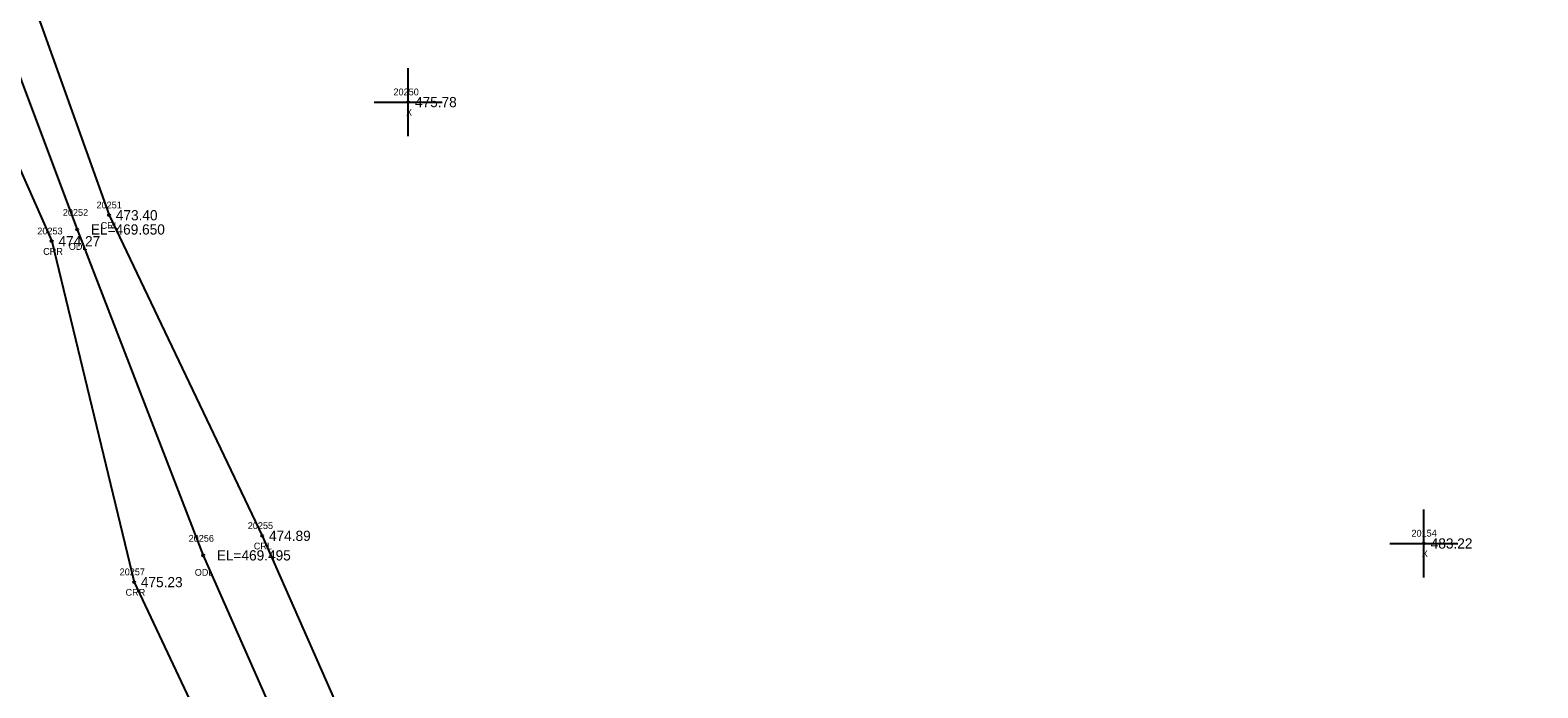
# Model space of a CAD drawing. Extents: x 1789565 to 1790548, y 909019 to 910194.
# Drawn here: x 1789950.9 to 1790172.5, y 909792.3 to 909888.9 of the extents above; entities that cross this region are included whole.
import ezdxf

# ---------------------------------------------------------------- set-up
doc = ezdxf.new("R2010")
doc.units = 0
for name, color, linetype in [('RD_EX_H2O', 7, 'Continuous'), ('RD_EX_H2O_txCode', 7, 'Continuous'), ('RD_EX_Misc', 7, 'Continuous'), ('RD_EX_Misc_txCode', 7, 'Continuous'), ('RD_EX_TX_H2O_ELEV', 7, 'Continuous'), ('RD_EX_TX_Misc_ELEV', 7, 'Continuous'), ('RD_SMD_Locator', 7, 'Continuous')]:
    doc.layers.add(name, color=color, linetype=linetype)

msp = doc.modelspace()

# ---------------------------------------------------------------- linework, layer by layer
at = {"layer": 'RD_EX_H2O'}
for points in [[(1789916.44, 910152.62), (1789911.22, 910059.17), (1789911.57, 910015.4), (1789913.25, 909950.04), (1789954.03, 909857.92), (1789966.14, 909807.85), (1790000.75, 909734.57), (1790025.55, 909650.06), (1790037.59, 909635.91)], [(1789926.75, 910151.78), (1789921.87, 910061.22), (1789923.33, 910015.8), (1789922.65, 909953.15), (1789957.79, 909859.65), (1789976.3, 909811.78), (1790009.05, 909737.59), (1790033.3, 909656.58), (1790043.84, 909640.77), (1790040.94, 909620.44), (1790068.41, 909598.88), (1790105.46, 909552.21), (1790128.28, 909493.4), (1790125.72, 909445.59), (1790167.31, 909436.17), (1790202.14, 909447.88), (1790216.41, 909437.36), (1790196.97, 909382.86), (1790209.47, 909371.8), (1790248.65, 909379.51), (1790333.47, 909404.65), (1790412.72, 909370.84), (1790438.82, 909377.48), (1790480.23, 909327.32)], [(1789942.19, 910149.47), (1789928.94, 910061.47), (1789937.03, 910016.56), (1789929.09, 909954.8), (1789962.46, 909861.74), (1789984.97, 909814.65), (1790017.82, 909740.15), (1790045.4, 909660.05), (1790055.69, 909646.96), (1790055.38, 909644.82), (1790053.69, 909634.91), (1790054.91, 909627.64), (1790075.55, 909607.72), (1790122.18, 909568.31), (1790142.55, 909490.86), (1790145.56, 909467.27), (1790204.21, 909464.64), (1790228.21, 909444.34), (1790208.83, 909385.44), (1790245.53, 909398.45), (1790340.56, 909420.98), (1790422.56, 909390.06), (1790444.95, 909390.88), (1790496, 909329.5)]]:
    msp.add_lwpolyline(points, dxfattribs=at)
at = {"layer": 'RD_EX_Misc'}
for p, q in [((1790006.43, 909873.35), (1790006.43, 909883.35)), ((1790001.43, 909878.35), (1790011.43, 909878.35)), ((1790155.73, 909808.53), (1790155.73, 909818.53)), ((1790150.73, 909813.53), (1790160.73, 909813.53))]:
    msp.add_line(p, q, dxfattribs=at)
at = {"layer": 'RD_SMD_Locator'}
for centre in [(1790006.43, 909878.35), (1789962.46, 909861.74), (1789957.79, 909859.65), (1789954.03, 909857.92), (1789984.97, 909814.65), (1790155.73, 909813.53), (1789976.3, 909811.78), (1789966.14, 909807.85)]:
    msp.add_circle(centre, 0.15, dxfattribs=at)

# ---------------------------------------------------------------- texts
at = {"layer": 'RD_EX_H2O_txCode'}
for s, p in [('20251', (1789960.62, 909862.74)), ('20252', (1789955.67, 909861.65)), ('20253', (1789951.92, 909858.92)), ('CRL', (1789961.23, 909859.74)), ('CRR', (1789952.78, 909855.92)), ('ODL', (1789956.54, 909856.65)), ('20256', (1789974.16, 909813.78)), ('20255', (1789982.85, 909815.65)), ('CRL', (1789983.74, 909812.65)), ('20257', (1789964.02, 909808.85)), ('ODL', (1789975.06, 909808.78)), ('CRR', (1789964.89, 909805.85))]:
    msp.add_text(s, height=1, dxfattribs=at).set_placement(p)
at = {"layer": 'RD_EX_Misc_txCode'}
for s, p in [('20250', (1790004.27, 909879.35)), ('X', (1790006.11, 909876.35)), ('20154', (1790153.9, 909814.53)), ('X', (1790155.42, 909811.53))]:
    msp.add_text(s, height=1, dxfattribs=at).set_placement(p)
at = {"layer": 'RD_EX_TX_H2O_ELEV'}
for s, p in [('473.40', (1789963.46, 909860.99)), ('EL=469.650', (1789959.79, 909858.9)), ('474.27', (1789955.03, 909857.17)), ('474.89', (1789985.97, 909813.9)), ('EL=469.495', (1789978.3, 909811.03)), ('475.23', (1789967.14, 909807.1))]:
    msp.add_text(s, height=1.5, dxfattribs=at).set_placement(p)
at = {"layer": 'RD_EX_TX_Misc_ELEV'}
for s, p in [('475.78', (1790007.43, 909877.6)), ('483.22', (1790156.73, 909812.78))]:
    msp.add_text(s, height=1.5, dxfattribs=at).set_placement(p)

doc.saveas('drawing.dxf')
